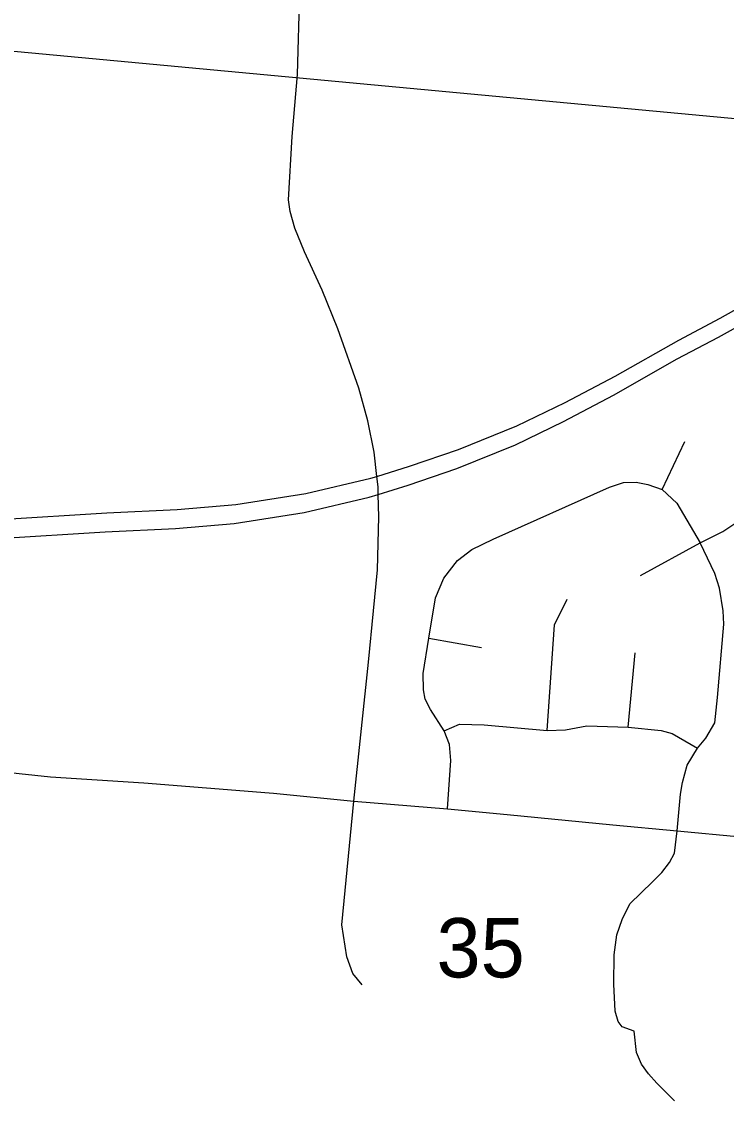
# Model space of a CAD drawing. Extents: x -38.1 to 35.9, y -2.7 to 28.5.
# Drawn here: x 10.024 to 10.521, y 13.559 to 14.335 of the extents above; entities that cross this region are included whole.
import ezdxf

# ---------------------------------------------------------------- set-up
doc = ezdxf.new("R2010")
doc.units = 0
for name, color, linetype in [('GM_X_City_Street', 7, 'Continuous'), ('GM_X_City_Street_Text', 7, 'Continuous'), ('GM_X_Corporation_Text', 7, 'Continuous'), ('GM_X_Minor_River', 7, 'Continuous'), ('GM_X_US_Route', 7, 'Continuous')]:
    doc.layers.add(name, color=color, linetype=linetype)

msp = doc.modelspace()

# ---------------------------------------------------------------- linework, layer by layer
at = {"layer": 'GM_X_City_Street'}
for p, q in [((10.47545, 14.00498), (10.49145, 14.03877)), ((10.46005, 13.94422), (10.50225, 13.96716)), ((10.31068, 13.89986), (10.34792, 13.89341)), ((10.45153, 13.83726), (10.45644, 13.88951))]:
    msp.add_line(p, q, dxfattribs=at)
for points in [[(10.26368, 13.65526), (10.25723, 13.66339), (10.2528, 13.67498), (10.24949, 13.69763), (10.25782, 13.78482), (10.26821, 13.88314), (10.27182, 13.91932), (10.2745, 13.94826), (10.2755, 13.98548), (10.27506, 14.00144), (10.27491, 14.00681), (10.27412, 14.01416), (10.27227, 14.03127), (10.2677, 14.05323), (10.26146, 14.07629), (10.24646, 14.11835), (10.23559, 14.14548), (10.22293, 14.17263), (10.21627, 14.18921), (10.21283, 14.20094), (10.21175, 14.20923), (10.21423, 14.2539), (10.218, 14.29782), (10.21972, 14.35681)], [(10.50225, 13.96716), (10.51838, 13.97533), (10.52883, 13.98223), (10.53493, 13.99029), (10.53812, 13.99679), (10.54376, 14.01579), (10.55737, 14.05994), (10.56231, 14.07277), (10.56987, 14.08054)], [(10.32395, 13.77944), (10.32639, 13.81375), (10.32537, 13.82485), (10.32168, 13.8345), (10.312, 13.84961), (10.30828, 13.85689), (10.30699, 13.86351), (10.30667, 13.875), (10.31068, 13.89986), (10.31556, 13.92851), (10.32138, 13.94225), (10.33108, 13.9547), (10.3411, 13.96262), (10.3563, 13.96989), (10.43826, 14.00643), (10.44813, 14.00983), (10.45718, 14.01015), (10.46543, 14.00837), (10.47545, 14.00498), (10.4858, 13.99528), (10.50225, 13.96716)], [(10.48416, 13.57357), (10.47174, 13.586), (10.46575, 13.59244), (10.46078, 13.59944), (10.45728, 13.60768), (10.45579, 13.62255), (10.44723, 13.62564), (10.44429, 13.62948), (10.44237, 13.63682), (10.44134, 13.6558), (10.44147, 13.67658), (10.44348, 13.69064), (10.44712, 13.70154), (10.45265, 13.71238), (10.46857, 13.72809), (10.47524, 13.73452), (10.48056, 13.74174), (10.48416, 13.74819), (10.48612, 13.76396), (10.48845, 13.7898), (10.48978, 13.79804), (10.49311, 13.8104), (10.50035, 13.82229), (10.50622, 13.82933), (10.51261, 13.84032), (10.51457, 13.85798), (10.51888, 13.90985), (10.51862, 13.91929), (10.51592, 13.93523), (10.51273, 13.94553), (10.50225, 13.96716)], [(10.39434, 13.83477), (10.39943, 13.9094), (10.40848, 13.9275)], [(10.32168, 13.8345), (10.33244, 13.83919), (10.34977, 13.83877), (10.39434, 13.83477), (10.40715, 13.83527), (10.42231, 13.83818), (10.45153, 13.83726), (10.47474, 13.83483), (10.48244, 13.83266), (10.50035, 13.82229)]]:
    msp.add_lwpolyline(points, dxfattribs=at)
at = {"layer": 'GM_X_City_Street_Text'}
for points in [[(9.82547, 13.78071), (9.83858, 13.79278), (9.85306, 13.80356), (9.86271, 13.80924), (9.87605, 13.81378), (9.89961, 13.81577), (9.94105, 13.81293), (9.98164, 13.80867), (10.0438, 13.80214), (10.10965, 13.79789), (10.19821, 13.79079), (10.20105, 13.79051)], [(10.20105, 13.79051), (10.25782, 13.78482), (10.32395, 13.77944), (10.36596, 13.77546), (10.44052, 13.76819), (10.48612, 13.76396), (10.53107, 13.7598), (10.63759, 13.7502), (10.67166, 13.74764), (10.74347, 13.74112), (10.85332, 13.73152), (10.91858, 13.72545), (11.00223, 13.7169), (11.09742, 13.70876), (11.14058, 13.70507), (11.19924, 13.69958), (11.28314, 13.69268), (11.33803, 13.68751), (11.35718, 13.68616)]]:
    msp.add_lwpolyline(points, dxfattribs=at)
at = {"layer": 'GM_X_Corporation_Text'}
for points in [[(9.26073, 13.94404), (9.48148, 13.95648), (9.70536, 13.96704), (9.83003, 13.9742), (9.88069, 13.9771), (10.00772, 13.98364), (10.08343, 13.98842), (10.13324, 13.99069), (10.17449, 13.99421), (10.22405, 14.00201), (10.26983, 14.01282), (10.27412, 14.01416), (10.29725, 14.02137), (10.33171, 14.03303), (10.37299, 14.04981), (10.40688, 14.06626), (10.44225, 14.08484), (10.48716, 14.11034), (10.51627, 14.1258), (10.54966, 14.14439)], [(9.83615, 13.96124), (9.87955, 13.96374), (10.00658, 13.97028), (10.08229, 13.97505), (10.1321, 13.97732), (10.17335, 13.98084), (10.22291, 13.98864), (10.26869, 13.99945), (10.27506, 14.00144), (10.29611, 14.00801), (10.33057, 14.01966), (10.37186, 14.03644), (10.40574, 14.05289), (10.44111, 14.07148), (10.48602, 14.09697), (10.51513, 14.11244), (10.54852, 14.13102)]]:
    msp.add_lwpolyline(points, dxfattribs=at)
at = {"layer": 'GM_X_US_Route'}
msp.add_lwpolyline([(9.97737, 14.31793), (10.9021, 14.23165), (10.81479, 13.2312), (9.82161, 13.32292), (9.87581, 14.07253)], close=True, dxfattribs=at)

# ---------------------------------------------------------------- texts
at = {"layer": 'GM_X_Minor_River'}
msp.add_text('35', height=0.041856, rotation=0.00001, dxfattribs=at).set_placement((10.31621, 13.66057))

doc.saveas('drawing.dxf')
